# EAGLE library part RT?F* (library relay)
Power PCB Relay SCHRACK bistable 1 pole 16 A, polarized bistable version Source: http://www.schrack.com/.. 5821.pdf
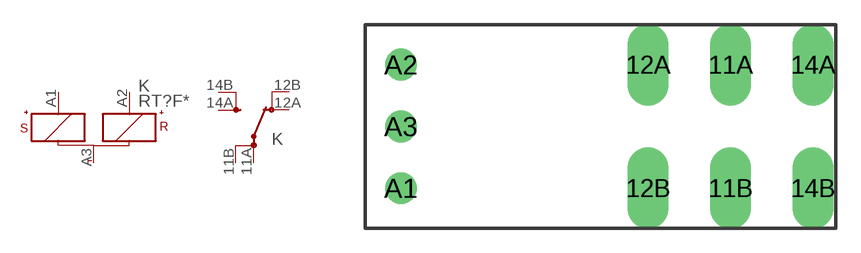
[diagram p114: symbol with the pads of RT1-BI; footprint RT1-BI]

Designator prefix K; gates 1=+KS+KR- 2=U-X2

## RT314F05 (MPN: RT314F05; OC_FARNELL: unknown; OC_NEWARK: 48M7949), RT314F06 (OC_FARNELL: unknown; OC_NEWARK: unknown), RT314F12 (MPN: RT314F12; OC_FARNELL: unknown; OC_NEWARK: 26M2701), RT314F24 (MPN: RT314F24; OC_FARNELL: 1175084; OC_NEWARK: 31M5918)  [RT1-BI]
11A  2:PA  pas
11B  2:PB  pas
12A  2:OA  pas
12B  2:OB  pas
14A  2:SA  pas
14B  2:SB  pas
A1  1:S+  pas
A2  1:R+  pas
A3  1:-  pas

## RTD14F05 (OC_FARNELL: unknown; OC_NEWARK: unknown), RTD14F06 (OC_FARNELL: unknown; OC_NEWARK: unknown), RTD14F12 (OC_FARNELL: unknown; OC_NEWARK: unknown), RTD14F24 (OC_FARNELL: unknown; OC_NEWARK: unknown)  [RT1-BI]
Pads as for RT1-BI

## Footprint RT1-BI (pad centres in mm)
Power PCB Relay , polarized bistable version SCHRACK 1 pole 16 A, pinning 5mm Source: http://www.schrack.com/.. 5821.pdf
drill 1.3 pad 2.5 long: 11A 7.56,3.78; 11B 7.56,-3.78; 12A 2.52,3.78; 12B 2.52,-3.78; 14A 12.6,3.78; 14B 12.6,-3.78
drill 1.3 round: A1 -12.6,-3.78; A2 -12.6,3.78; A3 -12.6,0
